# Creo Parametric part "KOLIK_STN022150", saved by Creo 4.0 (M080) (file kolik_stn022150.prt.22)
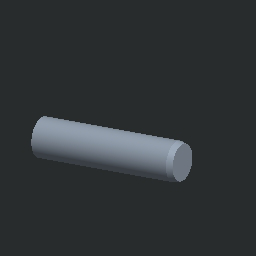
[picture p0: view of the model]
Units: Custom; MM, KILOGRAM, SECS
Materials in the file: OCEL_N

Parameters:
  PTC_MATERIAL_NAME = "OCEL_N"
  NAZOV = "KOLIK_STN022150"
  NORMA = "STN 02 2150"

Other parameters: HMOTNOST, HUSTOTA, D1

Created from: C022150.PRT

Layers: 1, 2, 3, 4, 5, 6, 7, 8, 9, 10, 11, 12, 13, 14, 15, 16, 17, 18, 19, 20, 21, 22, 23, 24, 25, 26, 27, 28, 29, 30, 31, 32

Family table entries: GENERIC, KOLIK_0_6, KOLIK_STN022150, value(d_val), value(i_val), KOLIK_0_8, KOLIK_STN022150, !/ , KOLIK_1, KOLIK_STN022150, KOLIK_1_2, KOLIK_STN022150, KOLIK_1_5, KOLIK_STN022150, KOLIK_2, KOLIK_STN022150, KOLIK_2_5, KOLIK_STN022150, KOLIK_3, KOLIK_STN022150, KOLIK_4, KOLIK_STN022150, KOLIK_5, KOLIK_STN022150, KOLIK_6, KOLIK_STN022150, KOLIK_8, KOLIK_STN022150, !/ , KOLIK_10, KOLIK_STN022150, !/$, KOLIK_12, KOLIK_STN022150, !/(, KOLIK_16, KOLIK_STN022150, !/0, KOLIK_20, KOLIK_STN022150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

Surfaces: 2 cone, 2 cylinder, 2 torus, 1 plane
